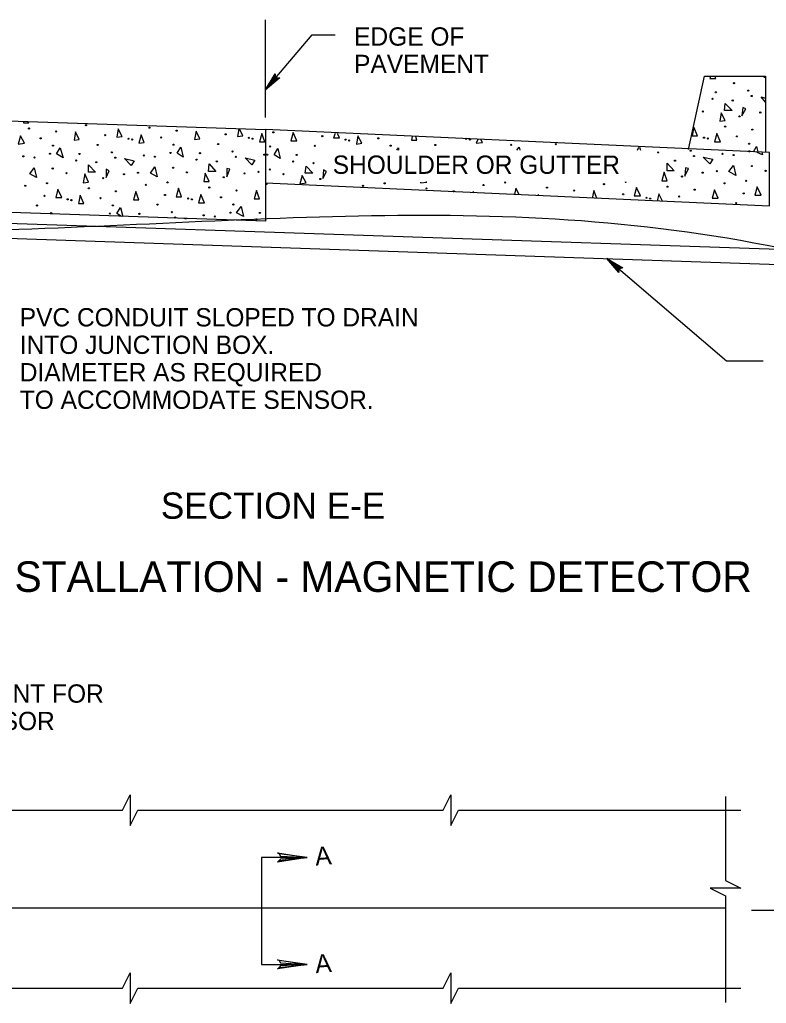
# Model space of a CAD drawing. Extents: x 2709 to 3899, y 22 to 1210.
# Drawn here: x 2908.4 to 3030.6, y 168.7 to 329.8 of the extents above; entities that cross this region are included whole.
import ezdxf

# ---------------------------------------------------------------- set-up
doc = ezdxf.new("R2010")
doc.units = 0
doc.layers.add('2', color=7, linetype='Continuous')
doc.layers.add('3', color=7, linetype='Continuous')

# ---------------------------------------------------------------- blocks, each defined once
blk = doc.blocks.new('RARROW')
at = {"layer": '3'}
blk.add_lwpolyline([(-2.2695, 0.285), (-2.184875, 0.12075), (0, 0), (-2.2695, 0.285), (-2.38575, 0.384625), (0, 0), (-2.183125, -0.108), (-2.262875, -0.2705), (0, 0), (-2.38575, -0.379125), (-2.262875, -0.2705)], dxfattribs=at)

msp = doc.modelspace()

# ---------------------------------------------------------------- linework, layer by layer
at = {"layer": '2'}
for p, q in [((2948.65, 313.79), (2948.65, 329.79)), ((2948.65, 318.29), (2956.28, 327.29)), ((2956.28, 327.29), (2960.03, 327.29)), ((2816.4, 299.54), (3040.28, 291.92)), ((2816.4, 297.04), (3040.28, 289.42)), ((3004.53, 290.67), (3024.15, 273.92)), ((3024.15, 273.92), (3030.15, 273.92)), ((2868.97, 184.29), (3023.97, 184.29))]:
    msp.add_line(p, q, dxfattribs=at)
for points in [[(3017.9, 308.54), (3020.53, 320.54), (3030.53, 320.54), (3030.53, 308.04), (3030.53, 308.04)], [(3021.53, 320.54), (3021.4, 320.17)], [(3021.4, 320.17), (3022.4, 320.17)], [(3022.4, 320.17), (3022.28, 320.54)], [(2801.15, 316.79), (2948.65, 311.79), (2948.65, 296.79), (2801.15, 301.79), (2801.15, 301.79)], [(3030.53, 316.29), (3029.78, 317.17)], [(3029.78, 317.17), (3030.53, 316.92)], [(2909.03, 313.04), (2909.03, 312.92)], [(2909.03, 312.92), (2909.9, 312.92)], [(2909.9, 312.92), (2909.78, 313.04)], [(2944.28, 311.92), (2944.03, 310.67)], [(2944.9, 310.79), (2944.4, 311.92)], [(2948.03, 311.17), (2947.65, 309.79)], [(2948.53, 309.79), (2948.03, 311.17)], [(2960.03, 311.17), (2959.78, 310.42)], [(2960.78, 310.42), (2960.4, 311.17)], [(3018.78, 312.17), (3018.53, 310.79)], [(3019.4, 310.79), (3018.78, 312.17)], [(2944.03, 310.67), (2944.9, 310.79)], [(2947.65, 309.79), (2948.53, 309.79)], [(2959.78, 310.42), (2960.78, 310.42)], [(2972.65, 310.67), (2972.53, 310.04)], [(2972.53, 310.04), (2973.4, 310.04)], [(2973.4, 310.04), (2973.28, 310.67)], [(2983.4, 310.17), (2983.15, 309.54)], [(2983.15, 309.54), (2984.15, 309.67)], [(2984.15, 309.67), (2983.9, 310.17)], [(3018.53, 310.79), (3019.4, 310.79)], [(2970.15, 308.42), (2970.4, 308.79), (2970.4, 308.42)], [(2989.78, 308.42), (2990.15, 308.92), (2990.28, 308.42)], [(3009.53, 308.42), (3009.78, 308.92)], [(3009.9, 308.92), (3010.03, 308.42)], [(3028.53, 308.17), (3029.03, 309.04)], [(3029.03, 309.04), (3029.28, 308.17)], [(3030.03, 307.67), (3029.15, 308.04)], [(3029.9, 308.04), (3030.03, 307.67)], [(2958.65, 304.92), (2958.15, 305.17), (2958.03, 303.79), (2958.65, 304.92)], [(2954.65, 304.29), (2954.28, 302.92)], [(2954.28, 302.92), (2955.28, 303.04)], [(2955.28, 303.04), (2954.65, 304.29)], [(2974.03, 303.17), (2974.03, 303.04), (2975.03, 303.17), (2974.9, 303.17)], [(2982.65, 301.67), (2982.65, 301.42)], [(2982.78, 301.42), (2982.65, 301.67)], [(2989.65, 302.17), (2989.4, 301.17)], [(2990.15, 301.17), (2989.65, 302.17)], [(3002.4, 301.79), (3002.15, 300.54)], [(3002.9, 300.54), (3002.4, 301.79)], [(2993.28, 301.17), (2993.28, 300.92)], [(2993.4, 300.92), (2993.28, 301.17)], [(3013.03, 301.29), (3012.78, 300.04)], [(3013.65, 300.04), (3013.03, 301.29)], [(2924.28, 298.04), (2924.9, 299.04)], [(2924.9, 299.04), (2925.28, 297.54)], [(2925.03, 297.54), (2924.28, 298.04)], [(2935.4, 297.17), (2935.28, 297.29)], [(2935.28, 297.29), (2935.65, 297.17)], [(2820.22, 200.29), (2872.72, 200.29), (2873.97, 202.79), (2873.97, 197.79), (2875.22, 200.29), (2925.22, 200.29), (2926.47, 202.79), (2926.47, 197.79), (2927.72, 200.29), (2977.72, 200.29), (2978.97, 202.79), (2978.97, 197.79), (2980.22, 200.29), (3026.47, 200.29)], [(3023.97, 202.54), (3023.97, 188.79), (3026.47, 187.54), (3021.47, 187.54), (3023.97, 186.29), (3023.97, 168.79)], [(2955.47, 192.54), (2947.97, 192.54), (2947.97, 180.04), (2947.97, 175.04), (2955.47, 175.04)], [(2950.85, 193.16), (2951.1, 192.79), (2955.47, 192.54), (2950.85, 193.16), (2950.6, 193.29), (2955.47, 192.54), (2951.1, 192.29), (2950.85, 192.04), (2955.47, 192.54), (2950.6, 191.79), (2950.85, 192.04)], [(3028.22, 183.91), (3035.72, 183.91), (3035.72, 191.41)], [(2950.85, 175.66), (2951.1, 175.29), (2955.47, 175.04), (2950.85, 175.66), (2950.6, 175.79), (2955.47, 175.04), (2951.1, 174.79), (2950.85, 174.54), (2955.47, 175.04), (2950.6, 174.29), (2950.85, 174.54)], [(2820.22, 171.16), (2872.72, 171.16), (2873.97, 173.66), (2873.97, 168.66), (2875.22, 171.16), (2925.22, 171.16), (2926.47, 173.66), (2926.47, 168.66), (2927.72, 171.16), (2977.72, 171.16), (2978.97, 173.66), (2978.97, 168.66), (2980.22, 171.16), (3026.47, 171.16)]]:
    msp.add_lwpolyline(points, dxfattribs=at)
for points in [[(3023.78, 314.92), (3023.9, 316.04), (3025.03, 314.92)], [(3023.28, 314.54), (3023.03, 313.17), (3023.9, 313.29)], [(3027.28, 315.17), (3026.78, 315.42), (3026.65, 314.04)], [(2917.53, 311.42), (2917.28, 310.04), (2918.15, 310.17)], [(2924.53, 311.92), (2924.28, 310.54), (2925.15, 310.67)], [(2937.28, 311.54), (2937.03, 310.17), (2937.9, 310.29)], [(3031.15, 308.04), (2948.65, 311.79), (2948.65, 303.04), (3031.15, 299.29)], [(2953.15, 311.29), (2952.78, 309.92), (2953.78, 309.92)], [(3022.53, 311.17), (3022.15, 309.79), (3023.15, 309.79)], [(2908.53, 310.79), (2908.15, 309.42), (2909.15, 309.54)], [(2928.28, 310.92), (2927.9, 309.54), (2928.78, 309.67)], [(2963.78, 310.79), (2963.53, 309.42), (2964.4, 309.54)], [(2914.4, 307.79), (2915.03, 308.79), (2915.53, 307.17)], [(2934.15, 307.92), (2934.78, 308.92), (2935.15, 307.29)], [(2950.03, 307.67), (2950.65, 308.67), (2951.03, 307.04)], [(2927.15, 306.67), (2926.65, 305.92), (2925.53, 307.04)], [(2939.28, 304.92), (2939.4, 306.17), (2940.53, 304.92)], [(2946.9, 306.79), (2946.4, 306.04), (2945.28, 307.17)], [(3014.4, 305.04), (3014.4, 306.29), (3015.53, 305.04)], [(3021.9, 306.92), (3021.4, 306.17), (3020.28, 307.29)], [(2910.03, 304.54), (2910.78, 305.54), (2911.15, 303.92)], [(2919.03, 304.54), (2918.78, 303.04), (2919.65, 303.17)], [(2919.65, 304.79), (2919.65, 306.04), (2920.78, 304.79)], [(2923.03, 305.04), (2922.53, 305.29), (2922.53, 303.92)], [(2929.78, 304.67), (2930.53, 305.67), (2930.9, 304.04)], [(2938.78, 304.67), (2938.53, 303.29), (2939.4, 303.29)], [(2942.78, 305.29), (2942.28, 305.42), (2942.28, 304.04)], [(2955.15, 304.67), (2955.28, 305.79), (2956.4, 304.67)], [(3013.9, 304.79), (3013.53, 303.42), (3014.4, 303.42)], [(3017.9, 305.42), (3017.4, 305.54), (3017.28, 304.17)], [(3024.53, 304.92), (3025.28, 305.92), (3025.65, 304.29)], [(2914.65, 302.04), (2914.28, 300.67), (2915.28, 300.67)], [(2927.4, 301.67), (2927.03, 300.29), (2927.9, 300.29)], [(2934.4, 302.17), (2934.03, 300.79), (2934.9, 300.79)], [(2947.15, 301.79), (2946.78, 300.42), (2947.65, 300.42)], [(3009.4, 302.29), (3009.03, 300.92), (3010.03, 300.92)], [(3022.15, 301.92), (3021.78, 300.54), (3022.78, 300.54)], [(3029.15, 302.42), (3028.78, 301.04), (3029.78, 301.04)], [(2918.28, 301.04), (2918.03, 299.67), (2918.9, 299.67)], [(2938.03, 301.17), (2937.65, 299.79), (2938.65, 299.79)], [(2943.9, 298.17), (2944.65, 299.17), (2945.03, 297.54)]]:
    msp.add_lwpolyline(points, close=True, dxfattribs=at)
for centre in [(3025.35, 319.39), (3030.39, 320.4), (3022.38, 317.9), (3027.69, 318.17), (3021.82, 316.83), (3025.14, 316.55), (3028.24, 317.3), (3020.24, 314.75), (3029.66, 314.58), (2919.24, 312.52), (3026.26, 313.95), (2909.9, 311.96), (2914.35, 311.48), (2929.63, 312.1), (2934.08, 311.62), (2942.11, 311.01), (2949.91, 311.33), (3023.9, 312.27), (3028.35, 311.79), (2911.82, 310.36), (2921.15, 309.28), (2922.37, 310.87), (2926.19, 310.29), (2926.79, 310.16), (2931.56, 310.5), (2933.57, 309.31), (2940.88, 309.42), (2945.92, 310.43), (2946.52, 310.3), (2957.94, 310.71), (2961.75, 310.14), (2962.35, 310), (2967.12, 310.35), (2981.49, 310.28), (2982.09, 310.14), (2988.87, 309.3), (2996.18, 309.41), (3020.45, 310.46), (3021.06, 310.33), (3025.83, 310.67), (3027.84, 309.48), (2913.35, 307.83), (2913.84, 309.17), (2918.18, 307.79), (2923.49, 308.06), (2933.09, 307.96), (2937.91, 307.93), (2943.22, 308.2), (2948.45, 307.69), (2948.92, 307.67), (2949.41, 309.02), (2956.71, 309.13), (2969.14, 309.16), (2976.45, 309.27), (3012.95, 308.05), (3018.26, 308.32), (3023.48, 307.81), (3027.86, 308.22), (2908.98, 307.41), (2910.8, 307.21), (2917.62, 306.73), (2920.93, 306.44), (2924.04, 307.19), (2928.72, 307.55), (2930.53, 307.35), (2937.35, 306.87), (2940.67, 306.58), (2943.77, 307.33), (2953.18, 306.57), (2953.74, 307.64), (2956.5, 306.29), (3015.7, 306.7), (3018.81, 307.45), (3025.3, 307.61), (2913.79, 305.41), (2916.04, 304.64), (2925.46, 304.47), (2927.76, 304.72), (2933.52, 305.55), (2935.77, 304.78), (2945.19, 304.61), (2947.5, 304.86), (2949.35, 305.26), (2951.6, 304.48), (3020.23, 304.73), (3022.53, 304.98), (3028.29, 305.81), (3030.54, 305.04), (2912.85, 303), (2922.06, 303.84), (2932.58, 303.14), (2941.79, 303.98), (2948.77, 302.86), (2957.62, 303.69), (2968.15, 302.98), (2987.88, 303.12), (3004.07, 302.85), (3016.83, 304.1), (3023.81, 302.99), (3027.35, 303.4), (2909.3, 302.59), (2919.7, 302.17), (2924.14, 301.68), (2929.04, 302.73), (2939.43, 302.3), (2943.88, 301.82), (2964.6, 302.57), (2975, 302.15), (2979.44, 301.67), (2984.34, 302.71), (2994.73, 302.29), (2999.18, 301.8), (3014.47, 302.43), (3018.91, 301.94), (3026.94, 301.33), (2912.44, 300.93), (2916.25, 300.36), (2916.85, 300.22), (2921.62, 300.56), (2932.17, 301.07), (2935.99, 300.49), (2936.59, 300.36), (2941.36, 300.7), (3007.21, 301.19), (3011.02, 300.62), (3011.62, 300.48), (3016.39, 300.82), (3025.72, 299.75), (2911.21, 299.35), (2913.55, 298.12), (2923.15, 298.03), (2923.64, 299.38), (2930.95, 299.49), (2933.29, 298.26), (2942.89, 298.17), (2943.37, 299.51), (2947.71, 298.13), (2927.98, 297.99), (2933.83, 297.39), (2938.51, 297.75), (2940.33, 297.55), (2947.15, 297.07)]:
    msp.add_circle(centre, 0.0919, dxfattribs=at)
msp.add_arc((3007.62, 303.26), 0.0919, 187.6668, 352.354, dxfattribs=at)
msp.add_spline([(2860.78, 296.79), (2870.78, 296.42), (2877.4, 295.92), (2887.15, 295.29), (2901.78, 295.29), (3039.53, 290.92), (3042.28, 290.54), (3046.03, 291.17), (3050.15, 290.92), (3050.15, 291.42), (3050.4, 293.79), (3051.65, 296.17), (3053.4, 297.67), (3055.65, 298.79), (3057.78, 299.42)], degree=3, dxfattribs=at)

# ---------------------------------------------------------------- block references
at = {"layer": '2', "xscale": 1.2574347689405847}
for p, yscale, rotation in [((2948.65, 318.29), 1.3092961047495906, -130.33386613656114), ((3004.53, 290.67), 1.3092961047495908, 139.88445274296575)]:
    msp.add_blockref('RARROW', p, dxfattribs=dict(at, yscale=yscale, rotation=rotation))

# ---------------------------------------------------------------- texts
at = {"layer": '2'}
for s, height, p in [('EDGE OF', 3, (2963.15, 325.54)), ('PAVEMENT', 3, (2963.15, 321.04)), ('SHOULDER OR GUTTER', 3, (2959.65, 304.54)), ('PVC CONDUIT SLOPED TO DRAIN', 3, (2908.4, 279.54)), ('INTO JUNCTION BOX.', 3, (2908.4, 275.04)), ('DIAMETER AS REQUIRED', 3, (2908.4, 270.54)), ('TO ACCOMMODATE SENSOR.', 3, (2908.4, 266.04)), ('SECTION E-E', 4.3, (2931.5, 248.04)), ('TYPICAL SENSOR INSTALLATION - MAGNETIC DETECTOR', 5, (2841.03, 236.06)), ('DRILL HOLE IN PAVEMENT FOR', 3, (2860.85, 217.91)), ('INSTALLATION OF SENSOR', 3, (2860.85, 213.41))]:
    msp.add_text(s, height=height, dxfattribs=at).set_placement(p)
for p in [(2956.87, 191.22), (2956.88, 173.59)]:
    msp.add_text('A', height=3, rotation=5, dxfattribs=at).set_placement(p)

doc.saveas('drawing.dxf')
